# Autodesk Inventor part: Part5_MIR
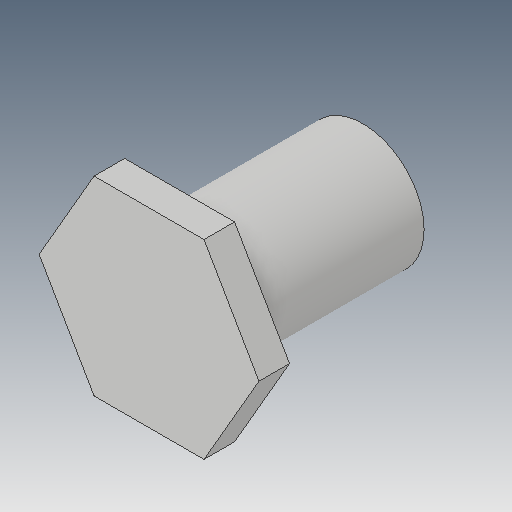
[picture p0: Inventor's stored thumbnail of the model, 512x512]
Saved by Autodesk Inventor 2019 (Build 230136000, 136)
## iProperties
Created: 2008-05
Part Number: Part5_MIR
Material: Generic
Document SubType Name: Modeling
Designer: CADCIM 00
Density: 1 g/cm^3
Appearance: Default
Author: CADCIM
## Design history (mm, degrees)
derived "Part5.ipt"
  sketch "Sketch1"
    geometry: C1 r 2 at (7.12, 11.618) reference
  sketch "Sketch2"
    geometry: L1 (3.598, 0)-(1.799, 3.116) reference; L2 (1.799, 3.116)-(-1.799, 3.116) reference; L3 (-1.799, 3.116)-(-3.598, 0) reference; L4 (-3.598, 0)-(-1.799, -3.116) reference; L5 (-1.799, -3.116)-(1.799, -3.116) reference; L6 (1.799, -3.116)-(3.598, 0) reference; C1 r 2 at (0, 0) reference; 1 further point
    constraints: 1 other
feature "Solid1::Part5.ipt" dims "d0" = 10
tag "TaggingFeature1"
body "Solid1"
